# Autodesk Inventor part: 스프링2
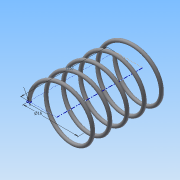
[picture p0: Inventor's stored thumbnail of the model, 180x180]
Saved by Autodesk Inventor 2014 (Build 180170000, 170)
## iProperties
Created: 2015-06
Part Number: 스프링2
Material: 강철, 연강
Document SubType Name: Modeling
Designer: Administrator
Density: 7.86 g/cm^3
Appearance: 강철
Mass: 1.53609 g
Surface Area: 7.89657 cm^2
Volume: 0.195431 cm^3
Author: Administrator
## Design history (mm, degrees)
sketch "스케치1"
  geometry: L1 (0, 0)-(-8, 0); L2 (-8, 0)-(-8, 21.5); L3 (-8, 21.5)-(0, 21.5); L4 (0, 21.5)-(0, 0); C1 r 0.5 at (-8, 0)
  constraints: 8 end point, 2 parallel, 1 centre point, 1 coincident, 1 horizontal, 1 perpendicular
  dimensions: "d0" = 1 diameter of C1; "d1" = 16 diameter of L2 L4; "d2" = 21.5 distance of L1.end L2.end (derived)
feature "코일1" sketch "스케치1" pitch "d3" = 10; turns "d5" = 5; dims "d4" = 21.5 (= d2), "d6" = 0, angle "d7" = 90 deg, angle "d8" = 90 deg, "d9" = 0, "d10" = 0
sketch "스케치2"
  geometry: L1 (8.5, 0)-(7.5, 0) reference; 1 further point
  constraints: 1 horizontal alignment
extrude "돌출1" cut sketch "스케치2" stored distance "d11" = 10; taper "d12" = 0 deg
node "작업 평면1"
sketch "스케치3"
  geometry: L1 (7.5, 0)-(8.5, 0) reference; 1 further point
  constraints: 1 horizontal alignment
extrude "돌출2" cut sketch "스케치3" stored distance "d14" = 10; taper "d15" = 0 deg
node "솔리드1"
node "절단 모서리 투영1"
node "절단 모서리 투영2"
other parameters: "d13" = 21.5 (= d2)
